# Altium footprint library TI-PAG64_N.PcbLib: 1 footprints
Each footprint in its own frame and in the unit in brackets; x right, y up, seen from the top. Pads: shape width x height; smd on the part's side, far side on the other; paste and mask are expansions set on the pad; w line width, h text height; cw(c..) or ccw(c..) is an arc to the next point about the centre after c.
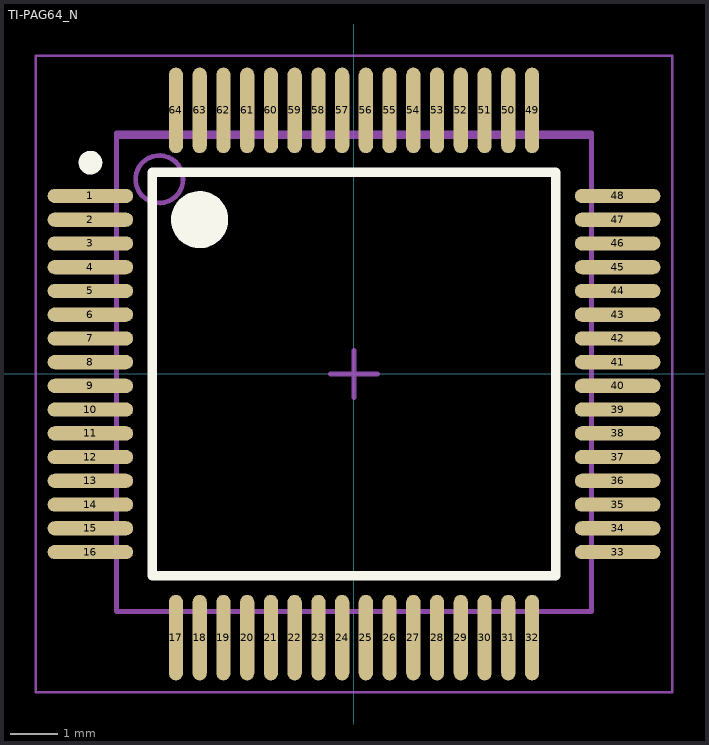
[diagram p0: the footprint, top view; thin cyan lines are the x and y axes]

## TI-PAG64_N [mm] "QFP, 64-Leads, Body 10x10mm, Pitch 0.5mm, IPC Medium Density"
height 1.2
pads (64):
  oval 1.8x0.3 smd: 1(-5.55,3.75) 2(-5.55,3.25) 3(-5.55,2.75) 4(-5.55,2.25) 5(-5.55,1.75) 6(-5.55,1.25) 7(-5.55,0.75) 8(-5.55,0.25) 9(-5.55,-0.25) 10(-5.55,-0.75) 11(-5.55,-1.25) 12(-5.55,-1.75) 13(-5.55,-2.25) 14(-5.55,-2.75) 15(-5.55,-3.25) 16(-5.55,-3.75) 33(5.55,-3.75) 34(5.55,-3.25) 35(5.55,-2.75) 36(5.55,-2.25) 37(5.55,-1.75) 38(5.55,-1.25) 39(5.55,-0.75) 40(5.55,-0.25) 41(5.55,0.25) 42(5.55,0.75) 43(5.55,1.25) 44(5.55,1.75) 45(5.55,2.25) 46(5.55,2.75) 47(5.55,3.25) 48(5.55,3.75)
  oval 0.3x1.8 smd: 17(-3.75,-5.55) 18(-3.25,-5.55) 19(-2.75,-5.55) 20(-2.25,-5.55) 21(-1.75,-5.55) 22(-1.25,-5.55) 23(-0.75,-5.55) 24(-0.25,-5.55) 25(0.25,-5.55) 26(0.75,-5.55) 27(1.25,-5.55) 28(1.75,-5.55) 29(2.25,-5.55) 30(2.75,-5.55) 31(3.25,-5.55) 32(3.75,-5.55) 49(3.75,5.55) 50(3.25,5.55) 51(2.75,5.55) 52(2.25,5.55) 53(1.75,5.55) 54(1.25,5.55) 55(0.75,5.55) 56(0.25,5.55) 57(-0.25,5.55) 58(-0.75,5.55) 59(-1.25,5.55) 60(-1.75,5.55) 61(-2.25,5.55) 62(-2.75,5.55) 63(-3.25,5.55) 64(-3.75,5.55)
Top Overlay:
  circle w0.25: c-5.55,4.45 r0.125
  circle w0.6: c-3.25,3.25 r0.3
  lines w0.2: -4.25,-4.25 -4.25,4.25 4.25,4.25 4.25,-4.25 -4.25,-4.25
Mechanical 13:
  circle w0.1: c-4.1,4.1 r0.5
  lines w0.1: -5,-5 -5,5 5,5 5,-5 -5,-5
Mechanical 15:
  lines w0.05: -6.7,-6.7 -6.7,6.7 6.7,6.7 6.7,-6.7 -6.7,-6.7
  lines w0.1: -0.5,0 0.5,0 ; 0,-0.5 0,0.5
Mechanical 31:
  lines w0.102: -5,-5 5,-5 5,5.08 -5,5.08 -5,-5
  text ".Comment" at -4.064,0.635 h0.76
  text ".Designator" at -4.064,1.905 h0.76
3D body "User Library-TQFP64_Grid_0_5.STEP": height 1.2, standoff 0, extent -6,-5.968 6,6.032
